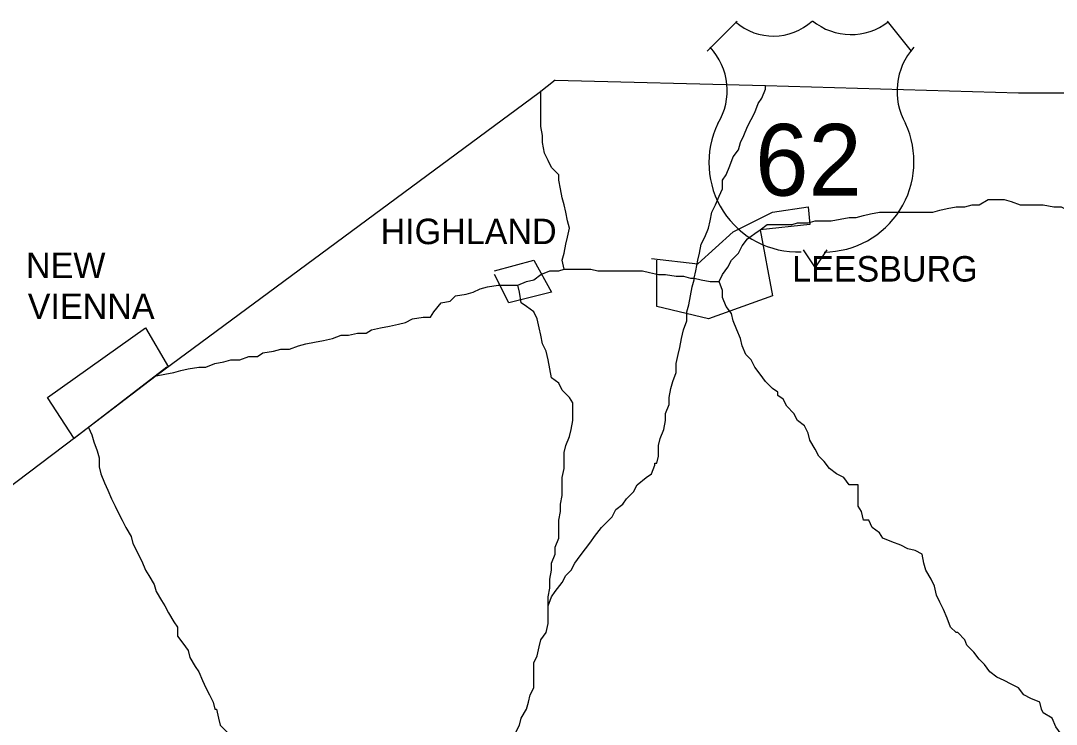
# Model space of a CAD drawing. Extents: x 0 to 40.2, y 0 to 22.
# Drawn here: x 3.548 to 4.34, y 18.847 to 19.385 of the extents above; entities that cross this region are included whole.
import ezdxf

# ---------------------------------------------------------------- set-up
doc = ezdxf.new("R2010")
doc.units = 0
doc.layers.add('Default', color=7, linetype='Continuous')

msp = doc.modelspace()

# ---------------------------------------------------------------- linework, layer by layer
at = {"layer": 'Default'}
for p, q in [((4.09617, 19.38506), (4.07316, 19.36205)), ((4.22962, 19.36205), (4.21121, 19.38506)), ((4.14679, 19.2102), (4.15599, 19.1964)), ((4.15599, 19.1964), (4.1652, 19.2102))]:
    msp.add_line(p, q, dxfattribs=at)
for points in [[(3.95693, 19.3399), (3.94466, 19.33035), (3.65153, 19.11357), (3.59972, 19.07403), (3.37066, 18.90087)], [(3.95693, 19.3399), (4.11782, 19.33581), (4.31142, 19.33035), (4.39459, 19.33035), (4.69591, 19.3249), (4.72318, 19.3249)], [(3.96375, 19.19537), (3.96239, 19.20219), (3.96375, 19.20764), (3.96511, 19.21446), (3.96648, 19.21992), (3.96784, 19.22673), (3.96648, 19.23219), (3.96511, 19.239), (3.96375, 19.24446), (3.96239, 19.24991), (3.96102, 19.25673), (3.95966, 19.26354), (3.95966, 19.26764), (3.95421, 19.27309), (3.95148, 19.27854), (3.94875, 19.284), (3.94739, 19.29218), (3.94739, 19.29763), (3.94603, 19.30445), (3.94603, 19.3099), (3.94603, 19.31672), (3.94603, 19.32354), (3.94603, 19.33035), (3.94603, 19.33172), (3.94603, 19.33172)], [(4.06328, 19.18856), (4.06464, 19.19401), (4.06601, 19.20219), (4.06737, 19.20764), (4.06873, 19.21446), (4.07146, 19.21992), (4.07419, 19.22673), (4.07555, 19.23219), (4.07691, 19.239), (4.07964, 19.24446), (4.08237, 19.25127), (4.08509, 19.25673), (4.08509, 19.26354), (4.08782, 19.26764), (4.09055, 19.27445), (4.09328, 19.28127), (4.09737, 19.28672), (4.09873, 19.29218), (4.10146, 19.29763), (4.10418, 19.30445), (4.10691, 19.3099), (4.10964, 19.31535), (4.11236, 19.32217), (4.11509, 19.32626), (4.11782, 19.33308), (4.11782, 19.33581)], [(4.03056, 19.20355), (4.06601, 19.19946), (4.09328, 19.22401), (4.12327, 19.239), (4.15054, 19.24309), (4.1519, 19.22946), (4.11373, 19.22537), (4.12327, 19.17492), (4.07419, 19.1572), (4.03465, 19.16674), (4.03465, 19.20219)], [(4.18735, 19.23491), (4.1928, 19.23628), (4.19826, 19.23764), (4.20508, 19.239), (4.21189, 19.239), (4.21871, 19.239), (4.22416, 19.239), (4.23234, 19.239), (4.2378, 19.239), (4.24598, 19.239), (4.25143, 19.24037), (4.25689, 19.24173), (4.2637, 19.24309), (4.27052, 19.24309), (4.27597, 19.24446), (4.28143, 19.24446), (4.28824, 19.24855), (4.29506, 19.24855), (4.30052, 19.24855), (4.30597, 19.24718), (4.31279, 19.24446), (4.31824, 19.24446), (4.3196, 19.24446)], [(4.3196, 19.24446), (4.32506, 19.24446), (4.33051, 19.24446), (4.33869, 19.24309), (4.34414, 19.24309), (4.3496, 19.24037), (4.35505, 19.23764), (4.36187, 19.23491), (4.36869, 19.23219), (4.37414, 19.23219), (4.37959, 19.23219), (4.38641, 19.23219), (4.39323, 19.23219), (4.39868, 19.23082), (4.4055, 19.22673), (4.41232, 19.22537), (4.41913, 19.22401), (4.42459, 19.22264), (4.4314, 19.22264), (4.43686, 19.22401), (4.43822, 19.22401)], [(4.08237, 19.18583), (4.08509, 19.19128), (4.08918, 19.19674), (4.09191, 19.20219), (4.09737, 19.20764), (4.10009, 19.2131), (4.10418, 19.21855), (4.10964, 19.22264), (4.11373, 19.22537), (4.11918, 19.22946), (4.12463, 19.22946), (4.13145, 19.22946), (4.13827, 19.22946), (4.14236, 19.23082), (4.15054, 19.23082), (4.15599, 19.23219), (4.16417, 19.23219), (4.16826, 19.23219), (4.17508, 19.23355), (4.1819, 19.23491), (4.18599, 19.23491), (4.18735, 19.23491)], [(3.91058, 19.19401), (3.94057, 19.20219), (3.95421, 19.17765), (3.92148, 19.16947), (3.91058, 19.19128)], [(3.9283, 19.1831), (3.93512, 19.18583), (3.94057, 19.18719), (3.94603, 19.19128), (3.95284, 19.19401), (3.95966, 19.19401), (3.96375, 19.19537), (3.96375, 19.19537)], [(3.9283, 19.1831), (3.93512, 19.18583), (3.94057, 19.18719), (3.94603, 19.19128), (3.95284, 19.19401), (3.95966, 19.19401), (3.96375, 19.19537), (3.96375, 19.19537)], [(3.96375, 19.19537), (3.97057, 19.19537), (3.97738, 19.19537), (3.9842, 19.19537), (3.98966, 19.19401), (3.99647, 19.19401), (4.00329, 19.19401), (4.00874, 19.19401), (4.01692, 19.19401), (4.02374, 19.19401), (4.02919, 19.19265), (4.03601, 19.19128), (4.04147, 19.19128), (4.04965, 19.18992), (4.0551, 19.18992), (4.06055, 19.18856), (4.06328, 19.18856)], [(4.03465, 19.04676), (4.03601, 19.05221), (4.03601, 19.0604), (4.03737, 19.06585), (4.0401, 19.07267), (4.04147, 19.07948), (4.04147, 19.08494), (4.04419, 19.09175), (4.04419, 19.09721), (4.04556, 19.10402), (4.04692, 19.10948), (4.04965, 19.1163), (4.04965, 19.12311), (4.05101, 19.12993), (4.05237, 19.13538), (4.05374, 19.1422), (4.0551, 19.14902), (4.05783, 19.15583), (4.05783, 19.16265), (4.05919, 19.16811), (4.06055, 19.17492), (4.06192, 19.18174), (4.06328, 19.18719), (4.06328, 19.18856)], [(4.06328, 19.18856), (4.06873, 19.18719), (4.07555, 19.18583), (4.08237, 19.18583)], [(3.77287, 19.13947), (3.77969, 19.14084), (3.78651, 19.1422), (3.79332, 19.14493), (3.79878, 19.14493), (3.80559, 19.14629), (3.81241, 19.14629), (3.8165, 19.14902), (3.82332, 19.15038), (3.83013, 19.15174), (3.83695, 19.15311), (3.84241, 19.15447), (3.84786, 19.1572), (3.85604, 19.15856), (3.86149, 19.15856), (3.86422, 19.16265), (3.86967, 19.16947), (3.87649, 19.17083), (3.88058, 19.17492), (3.88876, 19.17629), (3.89422, 19.17765), (3.89967, 19.18038), (3.90512, 19.18174), (3.9133, 19.1831), (3.91739, 19.1831), (3.92557, 19.1831), (3.9283, 19.1831), (3.9283, 19.1831)], [(3.97057, 19.09312), (3.96784, 19.09721), (3.96239, 19.10266), (3.95966, 19.10811), (3.95421, 19.11221), (3.95284, 19.11902), (3.95148, 19.12584), (3.95012, 19.13266), (3.94739, 19.13811), (3.94603, 19.14493), (3.94466, 19.15038), (3.9433, 19.1572), (3.94057, 19.16265), (3.93512, 19.16674), (3.93103, 19.16947), (3.92966, 19.17765), (3.9283, 19.1831), (3.9283, 19.1831)], [(4.12736, 19.1013), (4.12327, 19.10402), (4.11782, 19.10948), (4.11373, 19.11493), (4.10964, 19.12039), (4.10691, 19.12584), (4.10282, 19.12993), (4.10009, 19.13675), (4.09873, 19.1422), (4.096, 19.14902), (4.09328, 19.15583), (4.09191, 19.16129), (4.08782, 19.16674), (4.08509, 19.17356), (4.08509, 19.17901), (4.08237, 19.18583), (4.08237, 19.18583)], [(3.65971, 19.12039), (3.58881, 19.06585), (3.56836, 19.09721), (3.64335, 19.15038), (3.66107, 19.12039)], [(3.65153, 19.11357), (3.65834, 19.11493), (3.66516, 19.1163), (3.67061, 19.11766), (3.67607, 19.11902), (3.68425, 19.12039), (3.6897, 19.12039), (3.69652, 19.12311), (3.70334, 19.12448), (3.70879, 19.12584), (3.71561, 19.12584), (3.72242, 19.12857), (3.72924, 19.12857), (3.73333, 19.13129), (3.74151, 19.13266), (3.74697, 19.13402), (3.75378, 19.13402), (3.7606, 19.13675), (3.76605, 19.13811), (3.77287, 19.13947), (3.77287, 19.13947)], [(4.1928, 19.00313), (4.19144, 19.00995), (4.18871, 19.01404), (4.18871, 19.01949), (4.18871, 19.02358), (4.18871, 19.0304), (4.1819, 19.0304), (4.17781, 19.03585), (4.17235, 19.03858), (4.1669, 19.04267), (4.16281, 19.04812), (4.15872, 19.05221), (4.15599, 19.05767), (4.1519, 19.06449), (4.15054, 19.06994), (4.14781, 19.07539), (4.14236, 19.07948), (4.13963, 19.08494), (4.13418, 19.09039), (4.13145, 19.09584), (4.12736, 19.09857), (4.12736, 19.1013)], [(3.95148, 18.93769), (3.95148, 18.9445), (3.95284, 18.95132), (3.95284, 18.95814), (3.95421, 18.96496), (3.95421, 18.97041), (3.95693, 18.97723), (3.95693, 18.98268), (3.95966, 18.9895), (3.95966, 18.99768), (3.95966, 19.00313), (3.96102, 19.00995), (3.96102, 19.0154), (3.96239, 19.02222), (3.96239, 19.02904), (3.96239, 19.03585), (3.96375, 19.04267), (3.96375, 19.04812), (3.96375, 19.05494), (3.96511, 19.0604), (3.96784, 19.06721), (3.9692, 19.07267), (3.97057, 19.07948), (3.97057, 19.0863), (3.97057, 19.09175), (3.97057, 19.09312)], [(3.59972, 19.07403), (3.60244, 19.06858), (3.60381, 19.06312), (3.60653, 19.0563), (3.6079, 19.05085), (3.6079, 19.04403), (3.60926, 19.03858), (3.61199, 19.03176), (3.61471, 19.02631), (3.61744, 19.01949), (3.62017, 19.01404), (3.62289, 19.00859), (3.62562, 19.00313), (3.62835, 18.99768), (3.63244, 18.99086), (3.6338, 18.98541), (3.63517, 18.98268)], [(3.95148, 18.93769), (3.95421, 18.9445), (3.95693, 18.94859), (3.96239, 18.95541), (3.96511, 18.96087), (3.9692, 18.96496), (3.97193, 18.97041), (3.97602, 18.97586), (3.98011, 18.98132), (3.9842, 18.98677), (3.98693, 18.99086), (3.99238, 18.99768), (3.99511, 19.0004), (4.00056, 19.00586), (4.00329, 19.01131), (4.00874, 19.0154), (4.01147, 19.01949), (4.01692, 19.02495), (4.01965, 19.0304), (4.02647, 19.03585), (4.03056, 19.03858), (4.03328, 19.0454), (4.03328, 19.04676), (4.03465, 19.04676)], [(4.2637, 18.91724), (4.25961, 18.92133), (4.25689, 18.92814), (4.25416, 18.93496), (4.25143, 18.94041), (4.24871, 18.94587), (4.24734, 18.95268), (4.24461, 18.95814), (4.24052, 18.96496), (4.23916, 18.97041), (4.2378, 18.97723), (4.23234, 18.97995), (4.22689, 18.98132), (4.22144, 18.98404), (4.21462, 18.98677), (4.2078, 18.9895), (4.20508, 18.99359), (4.19962, 18.99768), (4.1969, 19.00313), (4.1928, 19.00313)], [(3.63517, 18.98268), (3.63789, 18.97723), (3.64062, 18.97177), (3.64335, 18.96496), (3.64607, 18.96087), (3.65016, 18.95405), (3.65153, 18.94859), (3.65562, 18.94178), (3.65834, 18.93769), (3.66107, 18.93223), (3.66516, 18.92542), (3.66789, 18.92133), (3.66789, 18.91451), (3.67198, 18.90906), (3.67607, 18.9036), (3.67743, 18.89815), (3.68152, 18.89133), (3.68425, 18.88724), (3.68698, 18.88042), (3.6897, 18.87497), (3.69243, 18.86952), (3.69516, 18.86406), (3.69652, 18.85861), (3.69788, 18.85861)], [(3.92694, 18.83407), (3.92694, 18.84088), (3.92966, 18.84634), (3.93103, 18.85179), (3.93512, 18.85861), (3.93648, 18.86406), (3.93785, 18.86952), (3.94057, 18.87497), (3.94057, 18.88315), (3.94057, 18.8886), (3.94057, 18.89406), (3.9433, 18.89951), (3.94466, 18.90633), (3.94603, 18.91178), (3.95012, 18.91724), (3.95148, 18.92405), (3.95148, 18.93087), (3.95148, 18.93769), (3.95148, 18.93769)], [(4.34687, 18.83407), (4.34414, 18.83952), (4.34005, 18.84497), (4.33733, 18.85179), (4.33051, 18.85588), (4.32915, 18.85861), (4.32778, 18.86406), (4.32097, 18.86679), (4.31551, 18.86952), (4.31142, 18.87497), (4.30597, 18.8777), (4.30052, 18.88042), (4.29506, 18.88315), (4.28961, 18.88724), (4.28552, 18.89269), (4.28143, 18.89678), (4.27734, 18.90224), (4.27188, 18.90769), (4.27052, 18.91178), (4.26507, 18.91724), (4.2637, 18.91724), (4.2637, 18.91724)], [(3.69788, 18.85861), (3.69925, 18.85179), (3.70061, 18.84634), (3.70606, 18.84088), (3.70743, 18.83407), (3.70879, 18.82861), (3.70879, 18.82316), (3.70879, 18.81771), (3.70879, 18.81089), (3.70879, 18.80407), (3.71015, 18.79862), (3.71152, 18.79316), (3.71424, 18.78635), (3.71561, 18.78089), (3.71697, 18.7768), (3.71697, 18.7768)]]:
    msp.add_lwpolyline(points, dxfattribs=at)
for centre, radius, start, end in [((4.12392, 19.41755), 0.04388, 228.71859, 312.45521), ((4.18339, 19.42127), 0.04643, 230.45249, 307.79333), ((4.04031, 19.33204), 0.04829, 328.44295, 43.21082), ((4.26912, 19.33154), 0.05055, 138.39443, 209.34239), ((4.14297, 19.27685), 0.06842, 154.0604, 271.92319), ((4.16241, 19.27756), 0.06913, 270.37171, 24.99189)]:
    msp.add_arc(centre, radius, start, end, dxfattribs=at)

# ---------------------------------------------------------------- texts
for s, height, p in [('62', 0.05486, (4.10998, 19.25161)), ('HIGHLAND', 0.019502, (3.82332, 19.21446)), ('NEW', 0.019502, (3.552, 19.18856)), ('LEESBURG', 0.019502, (4.13827, 19.18583)), ('VIENNA', 0.019502, (3.55336, 19.1572))]:
    msp.add_text(s, height=height, dxfattribs=at).set_placement(p)

doc.saveas('drawing.dxf')
